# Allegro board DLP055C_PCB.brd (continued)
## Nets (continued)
GND: C1.2 C2.1 C5.1 C6.1 C7.1 C8.2 C10.1 C14.2 C15.1 C18.1 C27.1 C34.2 C58.2 C59.2 C60.1 C69.1 C70.1 C71.2 C74.2 C91.2 C95.2 C96.2 C97.2 C108.2 C109.2 C110.2 C124.2 C126.2 C127.2 C130.2 C133.2 C136.2 C137.2 C138.1 C141.2 C147.2 C148.2 C149.2 C150.2 C151.1 C152.1 C153.2 C154.2 C155.2 C156.2 C157.2 C158.2 C159.2 C160.2 C161.1 C162.2 C163.2 C164.2 C165.2 C166.2 C167.2 C168.2 C169.2 C170.1 C171.2 C172.1 C173.2 C174.2 C175.1 C176.2 C177.2 C178.2 C179.2 C180.2 C181.2 C182.2 C183.2 C184.2 C185.2 C186.2 C187.2 C188.2 C189.2 C190.2 C191.2 C192.2 C193.2 C194.2 C195.2 C196.2 C197.2 C198.2 C199.2 C200.2 C201.2 C202.1 C203.2 C204.2 C205.2 C206.2 C207.2 C208.2 C209.2 C210.1 C211.1 C212.2 C213.2 C214.2 C215.2 C216.1 C217.2 C218.2 C219.2 C220.2 C221.2 C222.2 C223.2 C224.2 C225.2 C226.2 C227.2 C228.2 C229.2 C230.2 C231.1 C232.1 C233.2 C234.2 C235.2 C236.2 C237.2 C238.2 C239.2 C240.1 C241.2 C242.2 C243.2 C244.2 C245.2 C246.2 C247.2 C248.2 C249.2 C250.2 C251.2 C252.2 C253.2 C254.2 C255.2 C256.2 C257.2 C258.2 C259.1 C260.2 C261.2 C262.2 C263.2 C264.2 C265.2 C266.2 C267.2 C268.2 C269.2 C275.2 C276.2 C277.2 C278.2 C279.2 C280.2 C281.2 C282.2 C283.2 C284.2 C285.2 C286.2 C287.2 C288.2 C289.2 C290.2 C291.2 C298.1 C299.1 C300.2 C301.2 C302.2 C303.2 C304.2 C317.2 C320.2 C321.1 C502.1 C503.1 C504.1 C507.1 C508.1 C511.2 C514.2 C515.2 C517.2 C519.2 C520.1 C521.2 C528.1 C529.2 C530.1 C531.1 C547.2 C548.1 C549.2 C557.1 C576.1 C583.2 C585.2 C622.2 C623.2 C624.2 C625.2 C654.1 C664.1 C665.2 C666.1 C667.1 C668.2 C669.2 C670.2 C675.1 C676.1 C677.2 C678.2 C679.2 C682.1 C683.1 C684.1 C687.1 C688.1 C689.1 C690.1 C692.2 C694.2 C695.1 C696.1 C697.1 C698.1 C699.2 C700.1 C753.1 C754.1 C755.1 C757.2 C758.2 C759.2 C760.2 C761.2 C762.2 C763.2 C764.1 C765.1 C766.1 C770.1 C771.1 C772.1 C774.1 C775.1 C776.1 C778.2 C779.1 C783.1 C784.1 C785.1 C786.1 C788.1 C789.1 C790.1 C792.2 C793.1 C797.1 C798.1 C799.1 C800.1 C801.2 C802.2 C803.2 C804.2 C805.2 C806.1 C807.1 C808.1 C809.1 C810.1 C811.1 C814.1 C815.1 C816.1 C817.1 C818.1 C819.1 C820.2 C821.2 C822.2 C823.2 C824.2 C825.2 C826.2 C827.1 C828.1 C829.1 C830.1 C831.1 C832.1 C833.1 C834.1 C835.1 C836.1 C837.1 D30.1(ANODE) D32.1(ANODE) D35.1(ANODE) D36.1(ANODE) D37.1(ANODE) D38.1(ANODE) D39.1(ANODE) D40.1(ANODE) D41.1(ANODE) D42.1(ANODE) D43.1(ANODE) D44.1(ANODE) D45.1(ANODE) D46.1(ANODE) D47.1(ANODE) D48.1(ANODE) D50.3(ANODE) D51.1(ANODE) DN1.1 DN2.1 DN3.1 DN4.1 DN5.1 DN6.1 DN7.1 DN8.1 DN9.1 DN10.1 DN11.1 DN12.1 FB3.1 FB4.1 J2.5(GND) J2.6(C1) J2.7(C2) J2.8(C3) J2.9(C4) J3.5 J3.6 J3.8 J3.10 J3.15 J3.19 J3.24 J3.27 J3.30 J3.33 J3.36 J3.39 J3.42 J3.45 J3.48 J3.51 J3.52(GND#52) J3.53(GND#53) J3.54(GND#54) J3.55(GND#55) J3.56(GND#56) J3.57(GND#57) J3.58(GND#58) J3.59(GND#59) J3.60(GND#60) J3.61(GND#61) J3.62(GND#62) J3.63(GND#63) J4.2 J5.2 J6.1 J6.10 J7.1 J7.4 J7.5 J7.8 J7.9 J7.12 J7.13 J7.16 J7.17 J7.20 J7.21 J7.24 J7.25 J7.28 J7.29 J7.32 J7.33 J7.36 J7.39 J7.42 J7.52(GND#52) J7.53(GND#53) J7.54(GND#54) J7.55(GND#55) J7.56(GND#56) J7.57(GND#57) J7.58(GND#58) J7.59(GND#59) J7.60(GND#60) J7.61(GND#61) J7.62(GND#62) J7.63(GND#63) J8.2 J9.2 J10.1 J10.4 J10.5 J10.8 J10.9 J10.12 J10.13 J10.16 J10.17 J10.20 J10.21 J10.24 J10.25 J10.28 J10.29 J10.32 J10.33 J10.36 J10.39 J10.42 J10.50 J10.51 J10.52(GND#52) J10.53(GND#53) J10.54(GND#54) J10.55(GND#55) J10.56(GND#56) J10.57(GND#57) J10.58(GND#58) J10.59(GND#59) J10.60(GND#60) J10.61(GND#61) J10.62(GND#62) J10.63(GND#63) J11.2 J12.4 J16.4 J17.8(P8) J17.13(P13) J17.14(P14) J20.6 J21.1 J22.2 J23.1 J27.2 J28.3 J28.5 J28.7 J28.9 J28.11 J42.5 J42.6 J42.7 J42.9 J42.12 J42.15 J42.18 J42.21 J42.24 J42.27 J42.30 J42.33 J42.36 J42.39 J42.42 J42.45 J42.48 J42.52(GND#52) J42.53(GND#53) J42.54(GND#54) J42.55(GND#55) J42.56(GND#56) J42.57(GND#57) J42.58(GND#58) J42.59(GND#59) J42.60(GND#60) J42.61(GND#61) J42.62(GND#62) J42.63(GND#63) J43.14 J44.5 J44.6 J44.7 J44.8 J44.10 J44.13 J44.16 J44.19 J44.22 J44.25 J44.27 J44.33 J44.39 J44.43 J44.45 J44.48 J44.52(GND#52) J44.53(GND#53) J44.54(GND#54) J44.55(GND#55) J44.56(GND#56) J44.57(GND#57) J44.58(GND#58) J44.59(GND#59) J44.60(GND#60) J44.61(GND#61) J44.62(GND#62) J44.63(GND#63) J45.2 J51.3 J62.2 J69.9 J69.10 J69.14 J70.9(P9) J73.1 J74.4 J83.4(GND) J83.5(C1) J83.6(C2) J85.3 J96.12 J97.7 J97.10 J97.15 J97.16 J102.5 J103.1 J104.1 J105.1 J110.1 J110.14 J111.6(P6) J112.6(P6) J113.6(P6) J114.3 J115.1 J120.6 J120.10 J120.11 J120.12 J121.6 J121.10 J121.11 J121.12 J122.7 J500.1 J500.3 J500.5 J500.7 J500.9 J500.11 J500.13 J500.15 J500.17 J500.19 J500.21 J500.23 J500.25 J500.27 J500.29 J500.31 J500.33 J500.35 J500.37 J500.39 J500.41 J500.43 J500.45 J500.47 J500.49 J500.51 J500.52(GND#52) J500.53(GND#53) J500.54(GND#54) J500.55(GND#55) J500.56(GND#56) J500.57(GND#57) J500.58(GND#58) J500.59(GND#59) J500.60(GND#60) J500.61(GND#61) J500.62(GND#62) J500.63(GND#63) J501.4 J501.6 J501.8 J501.10 J501.12 J501.14 J501.16 J501.18 J501.20 J503.1 J506.2 J516.2 J517.2 J518.2 J520.2 J521.2 J522.2 J524.2 J525.2 J526.2 J532.3 J533.3 J535.3 J536.4 Q1.2(E) Q6.2(SOURCE) Q13.2(SOURCE) R2.2(N2) R11.2(N2) R36.2(N2) R62.2(N2) R63.2(N2) R88.2(N2) R90.1(N1) R95.1(N1) R96.1(N1) R97.1(N1) R99.1(N1) R100.1(N1) R101.1(N1) R103.1(N1) R105.2(N2) R106.2(N2) R108.1 R113.1(N1) R114.1(N1) R120.2(N2) R123.2(N2) R133.2(N2) R138.2(N2) R144.2(N2) R145.2(N2) R148.2(N2) R149.2(N2) R155.1(N1) R157.2(N2) R198.1 R210.2(N2) R523.2(N2) R524.1(N1) R525.1(N1) R544.2(N2) R545.2(N2) R581.1(N1) R586.1(N1) R590.1(N1) R593.1(N1) R594.1(N1) R595.1(N1) R629.2(N2) R632.2(N2) R640.2(N2) R642.2(N2) R643.2(N2) R644.2(N2) R645.2(N2) R646.2(N2) R648.2(N2) R649.2(N2) R660.2(N2) R661.2(N2) R662.2(N2) R663.2(N2) R664.2(N2) R665.2(N2) R666.2(N2) R667.2(N2) R712.2(N2) R713.2(N2) R714.2(N2) R715.2(N2) R747.1 R751.1 R776.1 R797.1 R818.1 R821.1 R827.1 R828.2 R829.1 R830.2 R838.2 R839.1 R859.2(N2) R865.2(N2) SW5.3 TP1.1(P1) TP2.1(P1) TP11.1(P1) TP14.1(P1) TP38.1(P1) TP39.1(P1) U1.4(GND) U2.3(GND) U3.3(GND) U4.33(GND#33) U4.52(GND#52) U7.2(PGND) U7.5(GND) U7.11(PAD) U8.33(GND#33) U8.52(GND#52) U9.1(O\E\) U9.3(GND) U11.3(GND) U12.3(GND) U13.3(GND) U14.3(GND) U15.A1(VSS#A1) U15.A2(VSS#A2) U15.A3(VSS#A3) U15.A5(VSS#A5) U15.A7(VSS#A7) U15.A9(VSS#A9) U15.A11(VSS#A11) U15.A13(VSS#A13) U15.A15(VSS#A15) U15.A18(VSS#A18) U15.A20(VSS#A20) U15.A22(VSS#A22) U15.A24(VSS#A24) U15.A26(VSS#A26) U15.A28(VSS#A28) U15.A29(USB_XI) U15.A30(VSS#A30) U15.AA25(VSS#AA25) U15.AA28(VSS#AA28) U15.AB1(VSS#AB1) U15.AB6(VSS#AB6) U15.AB30(VSS#AB30) U15.AC3(VSS#AC3) U15.AC25(VSS#AC25) U15.AC27(VSS#AC27) U15.AD6(VSS#AD6) U15.AE1(VSS#AE1) U15.AE5(VSS#AE5) U15.AE7(VSS#AE7) U15.AE9(VSS#AE9) U15.AE11(VSS#AE11) U15.AE15(VSS#AE15) U15.AE17(VSS#AE17) U15.AE21(VSS#AE21) U15.AE23(VSS#AE23) U15.AE25(VSS#AE25) U15.AE26(VSS#AE26) U15.AE28(VSS#AE28) U15.AF3(VSS#AF3) U15.AF5(VSS#AF5) U15.AF6(VSS#AF6) U15.AF8(VSS#AF8) U15.AF10(VSS#AF10) U15.AF12(VSS#AF12) U15.AF14(VSS#AF14) U15.AF15(VSS#AF15) U15.AF17(VSS#AF17) U15.AF18(VSS#AF18) U15.AF19(VSS#AF19) U15.AF20(VSS#AF20) U15.AF22(VSS#AF22) U15.AF24(VSS#AF24) U15.AF26(VSS#AF26) U15.AF28(VSS#AF28) U15.AF30(VSS#AF30) U15.AG4(VSS#AG4) U15.AG6(VSS#AG6) U15.AG8(VSS#AG8) U15.AG10(VSS#AG10) U15.AG12(VSS#AG12) U15.AG14(VSS#AG14) U15.AG16(VSS#AG16) U15.AG18(VSS#AG18) U15.AG23(VSS#AG23) U15.AG25(VSS#AG25) U15.AG27(VSS#AG27) U15.AG29(VSS#AG29) U15.AH1(VSS#AH1) U15.AH2(VSS#AH2) U15.AH3(VSS#AH3) U15.AH4(VSS#AH4) U15.AH6(VSS#AH6) U15.AH8(VSS#AH8) U15.AH10(VSS#AH10) U15.AH12(VSS#AH12) U15.AH14(VSS#AH14) U15.AH16(VSS#AH16) U15.AH18(VSS#AH18) U15.AH21(VSS#AH21) U15.AH23(VSS#AH23) U15.AH25(VSS#AH25) U15.AH27(VSS#AH27) U15.AH29(VSS#AH29) U15.AH30(VSS#AH30) U15.AJ1(VSS#AJ1) U15.AJ3(VSS#AJ3) U15.AJ5(VSS#AJ5) U15.AJ7(VSS#AJ7) U15.AJ9(VSS#AJ9) U15.AJ11(VSS#AJ11) U15.AJ13(VSS#AJ13) U15.AJ15(VSS#AJ15) U15.AJ17(VSS#AJ17) U15.AJ22(VSS#AJ22) U15.AJ24(VSS#AJ24) U15.AJ26(VSS#AJ26) U15.AJ28(VSS#AJ28) U15.AJ30(VSS#AJ30) U15.AK1(VSS#AK1) U15.AK3(VSS#AK3) U15.AK5(VSS#AK5) U15.AK7(VSS#AK7) U15.AK9(VSS#AK9) U15.AK11(VSS#AK11) U15.AK13(VSS#AK13) U15.AK15(VSS#AK15) U15.AK17(VSS#AK17) U15.AK22(VSS#AK22) U15.AK24(VSS#AK24) U15.AK26(VSS#AK26) U15.AK28(VSS#AK28) U15.AK30(VSS#AK30) U15.B1(VSS#B1) U15.B2(VSS#B2) U15.B3(VSS#B3) U15.B5(VSS#B5) U15.B7(VSS#B7) U15.B9(VSS#B9) U15.B11(VSS#B11) U15.B13(VSS#B13) U15.B18(VSS#B18) U15.B20(VSS#B20) U15.B22(VSS#B22) U15.B24(VSS#B24) U15.B26(VSS#B26) U15.B28(VSS#B28) U15.B30(VSS#B30) U15.C3(VSS#C3) U15.C4(VSS#C4) U15.C6(VSS#C6) U15.C8(VSS#C8) U15.C10(VSS#C10) U15.C12(VSS#C12) U15.C14(VSS#C14) U15.C17(VSS#C17) U15.C19(VSS#C19) U15.C21(VSS#C21) U15.C23(VSS#C23) U15.C25(VSS#C25) U15.C29(VSS#C29) U15.D1(VSS#D1) U15.D2(VSS#D2) U15.D6(VSS#D6) U15.D8(VSS#D8) U15.D10(VSS#D10) U15.D12(VSS#D12) U15.D14(VSS#D14) U15.D17(VSS#D17) U15.D19(VSS#D19) U15.D21(VSS#D21) U15.D23(VSS#D23) U15.D25(VSS#D25) U15.D28(VSS#D28) U15.E3(VSS#E3) U15.E4(VSS#E4) U15.E5(VSS#E5) U15.E7(VSS#E7) U15.E9(VSS#E9) U15.E11(VSS#E11) U15.E13(VSS#E13) U15.E15(VSS#E15) U15.E20(VX1_CM_CKREF0) U15.E21(VX1_CM_CKREF1) U15.E22(VSS#E22) U15.E23(VX1_CM_CKREF2) U15.E24(VX1_CM_CKREF3) U15.E25(VSS#E25) U15.E28(VSS#E28) U15.F1(VSS#F1) U15.F2(VSS#F2) U15.F5(VSS#F5) U15.F6(VSS#F6) U15.F8(VSS#F8) U15.F10(VSS#F10) U15.F12(VSS#F12) U15.F13(VSS#F13) U15.F17(VSS#F17) U15.F18(VSS#F18) U15.F20(VSS#F20) U15.F30(VSS#F30) U15.G3(VSS#G3) U15.G4(VSS#G4) U15.G5(VSS#G5) U15.G25(VPGM) U15.G27(VSS#G27) U15.H1(VSS#H1) U15.H2(VSS#H2) U15.H5(VSS#H5) U15.H6(VSS#H6) U15.J3(VSS#J3) U15.J4(VSS#J4) U15.J5(VSS#J5) U15.J25(VSS#J25) U15.J28(VSS#J28) U15.K6(VSS#K6) U15.K30(VSS#K30) U15.L1(VSS#L1) U15.L25(VSS#L25) U15.L26(HWTEST_EN) U15.L27(VSS#L27) U15.M3(VSS#M3) U15.M6(VSS#M6) U15.M12(VSS#M12) U15.M13(VSS#M13) U15.M14(VSS#M14) U15.M15(VSS#M15) U15.M16(VSS#M16) U15.M17(VSS#M17) U15.M18(VSS#M18) U15.M19(VSS#M19) U15.M26(ICTSE) U15.N1(VSS#N1) U15.N12(VSS#N12) U15.N13(VSS#N13) U15.N14(VSS#N14) U15.N15(VSS#N15) U15.N16(VSS#N16) U15.N17(VSS#N17) U15.N18(VSS#N18) U15.N19(VSS#N19) U15.N25(VSS#N25) U15.N28(VSS#N28) U15.P6(VSS#P6) U15.P12(VSS#P12) U15.P13(VSS#P13) U15.P14(VSS#P14) U15.P15(VSS#P15) U15.P16(VSS#P16) U15.P17(VSS#P17) U15.P18(VSS#P18) U15.P19(VSS#P19) U15.P30(VSS#P30) U15.R3(VSS#R3) U15.R12(VSS#R12) U15.R13(VSS#R13) U15.R14(VSS#R14) U15.R15(VSS#R15) U15.R16(VSS#R16) U15.R17(VSS#R17) U15.R18(VSS#R18) U15.R19(VSS#R19) U15.R25(VSS#R25) U15.R27(VSS#R27) U15.T1(VSS#T1) U15.T6(VSS#T6) U15.T12(VSS#T12) U15.T13(VSS#T13) U15.T14(VSS#T14) U15.T15(VSS#T15) U15.T16(VSS#T16) U15.T17(VSS#T17) U15.T18(VSS#T18) U15.T19(VSS#T19) U15.U3(VSS#U3) U15.U5(VSS#U5) U15.U12(VSS#U12) U15.U13(VSS#U13) U15.U14(VSS#U14) U15.U15(VSS#U15) U15.U16(VSS#U16) U15.U17(VSS#U17) U15.U18(VSS#U18) U15.U19(VSS#U19) U15.U25(VSS#U25) U15.U28(VSS#U28) U15.V6(VSS#V6) U15.V12(VSS#V12) U15.V13(VSS#V13) U15.V14(VSS#V14) U15.V15(VSS#V15) U15.V16(VSS#V16) U15.V17(VSS#V17) U15.V18(VSS#V18) U15.V19(VSS#V19) U15.V30(VSS#V30) U15.W1(VSS#W1) U15.W5(VSS#W5) U15.W12(VSS#W12) U15.W13(VSS#W13) U15.W14(VSS#W14) U15.W15(VSS#W15) U15.W16(VSS#W16) U15.W17(VSS#W17) U15.W18(VSS#W18) U15.W19(VSS#W19) U15.W25(VSS#W25) U15.W27(VSS#W27) U15.Y3(VSS#Y3) U15.Y6(VSS#Y6) U16.3(GND) U17.4(GND) U18.3(GND) U19.3(GND) U20.3(GND) U26.14(AVSS1) U26.19(DVSS1) U26.49(DVSS2) U26.61(VSSU) U26.68(AVSS2) U27.2(GND) U30.4(GND) U30.7(WP) U32.7(PGND#7) U32.8(PGND#8) U32.10(NC1) U32.13(AGND) U32.16(NC2) U32.18(PGND#18) U32.21(PAD) U33.3(GND) U34.2(GND) U35.13(GND) U35.17(PAD) U36.2(GND) U37.2(GND) U38.2(I) U38.3(GND) U39.3(GND) U40.3(GND) U42.3(GND) U43.1(O\E\1\) U43.12(GND) U43.13(O\E\2\) U46.15(GND) U47.1(O\E\) U47.3(GND) U48.3(GND) U49.1(O\E\1\) U49.12(GND) U49.13(O\E\2\) U51.1(1O\E\) U51.4(GND#4) U51.10(GND#10) U51.15(GND#15) U51.21(GND#21) U51.24(4O\E\) U51.25(3O\E\) U51.26(4A4) U51.27(4A3) U51.28(GND#28) U51.34(GND#34) U51.39(GND#39) U51.45(GND#45) U51.48(2O\E\) U53.2 U54.2 U55.3(GND) U58.3(GND) U59.11(THERM_PAD) U500.2(GND) U501.4(GND) U502.2(GND) U503.4(GND) U520.3(GND) U521.11(THERM_PAD) U523.2(S) U524.5(GND) U524.9(GND_PAD) U525.3(GND) U525.4(INV) U526.3(GND) U527.2(S) U528.2(S) U529.3(GND) U538.4(V-) U539.4(V-) U555.7(GND#7) U555.19(GND#19) U555.44(GND#44) U555.49(PAD) U556.7(GND#7) U556.19(GND#19) U556.44(GND#44) U556.49(PAD) U557.7(GND#7) U557.19(GND#19) U557.44(GND#44) U557.49(PAD) U558.3(GND) U559.2(GND) U560.1(A0) U560.2(A1) U560.3(A2) U560.4(GND) U561.2(GND) U562.4(VSSD#4) U562.17(VSSD#17) U562.20(VSSD#20) U562.24(VSSA) U562.33(PAD) U563.3(GND) U564.3(GND) U565.3(GND) U566.4(V-) U567.1(O\E\) U567.3(GND) U568.3(GND) U569.3(GND) VR1.1(A) VR2.1(A) VR3.1(A) X1.2(NC1) X1.4(NC2) X2.2(NC1) X2.4(NC2)
P5V: C507.2 C764.2 J28.1 J60.1 J67.1 R755.1 TP232.1
P5V_FP_FE: J42.1 J42.2 J42.3 J42.4 J60.2
P5V_VX1_FE: J3.1 J3.2 J3.3 J3.4 J67.2
P12V: C1.1 C8.1 C58.1 C59.1 C71.1 C124.1 C130.1 C802.1 C803.1 C804.1 C805.1 C806.2 C807.2 C808.2 C830.2 J4.1 J5.1 J8.1 J97.2 J114.1 J120.1 J120.2 J121.1 J121.2 R80.2(N2) R246.1(N1) TP247.1 U32.2(VIN#2) U32.3(VIN#3) U32.4(VIN#4) U32.5(VIN#5) U59.3(VIN#3) U59.4(VIN#4) U59.5(VIN#5) U522.5(D#5) U522.6(D#6) U522.7(D#7) U522.8(D#8)
P12V_CNTL_D: Q13.3(DRAIN) R825.1 R826.2
P12V_CNTL_G: C809.2 D50.2(CATHODE) D51.3(CATHODE) Q13.1(GATE) R824.1 R830.1 SW5.1
P12V_DLPA100: C752.2 C753.2 C754.2 C755.2 C773.2 C774.2 C775.2 C776.2 C787.2 C788.2 C789.2 C790.2 C821.1 C822.1 C823.1 C824.1 C825.1 C826.1 C827.2 C828.2 C829.2 DN1.2 DN2.2 DN3.2 DN4.2 DN5.2 DN6.2 DN7.2 DN8.2 DN9.2 DN10.2 DN11.2 DN12.2 R739.2 R778.2 R779.1 R780.1 R781.2 R782.1 R799.2 R800.1 R801.1 R802.2 R803.1 TP249.1 U59.6(OUT#6) U59.7(OUT#7) U59.8(OUT#8) U555.9(VBB3) U555.22(VBB1) U555.27(ISENK) U555.37(VBB2) U555.42(VBB4) U556.9(VBB3) U556.22(VBB1) U556.27(ISENK) U556.37(VBB2) U556.42(VBB4) U557.9(VBB3) U557.22(VBB1) U557.27(ISENK) U557.37(VBB2) U557.42(VBB4)
P12V_DRV: C133.1 C320.1 R80.1(N1) U35.12(VM)
P12V_REF: D50.1(REFERENCE) R823.1 R829.2
P12V_SEQ_EN: R198.2 U58.4(Y) U59.2(EN/UVLO)
P12V_SW_G: D49.1(ANODE) Q12.G(GATE) R822.1 R825.2
P12V_VIN: C60.2 C810.2 C811.2 J527.1 J528.1 Q12.D1(DRAIN1) Q12.D2(DRAIN2) R820.2 R833.2 TP245.1 U521.3(VIN#3) U521.4(VIN#4) U521.5(VIN#5) U524.8(VIN)
VBUS: TP76.1(P1) U26.65(VBUS)
VDD33_FPD: C170.2 C230.1 C255.1 C258.1 C265.1 C266.1 C267.1 C287.1 C288.1 C289.1 L506.2 U15.E6(VDD33_FPD#E6) U15.E8(VDD33_FPD#E8) U15.E10(VDD33_FPD#E10) U15.E12(VDD33_FPD#E12) U15.E14(VDD33_FPD#E14) U15.G6(VDD33_FPD#G6) U15.L11(VDD33_FPD#L11) U15.L13(VDD33_FPD#L13)
VDD115_FPD: C257.1 C259.2 C262.1 C263.1 C264.1 C284.1 C286.1 L505.1 U15.F7(VDD115_FPD#F7) U15.F9(VDD115_FPD#F9) U15.F11(VDD115_FPD#F11) U15.J6(VDD115_FPD#J6) U15.L12(VDD115_FPD#L12)
VDD115_HSSI0_PLL: C155.1 C159.1 L13.1 U15.AE22(VDD115_HSSI0_PLL)
VDD115_HSSI1_PLL: C236.1 C239.1 L24.1 U15.AE10(VDD115_HSSI1_PLL)
VDD115_PLLMA: C180.1 C182.1 L16.1 U15.AE18(VDD115_PLLMA)
VDD115_PLLMB: C224.1 C228.1 L22.1 U15.F15(VDD115_PLLMB)
VDD115_PLLS: C226.1 C229.1 L21.1 U15.F16(VDD115_PLLS)
3D_LR: J61.2 J62.1 TP212.1(P1)
3D_REF: J44.3 U15.D15(FPDC_DATAE_N)
38MHZ_I: C232.2 R118.1(N1) X2.1
38MHZ_O: C231.2 R117.1(N1) X2.3
40MHZ_CLK0: J500.26 R669.2(N2) R706.1(N1)
40MHZ_I: C69.2 R30.1(N1) X1.1
40MHZ_O: C70.2 R31.1(N1) X1.3
40MHZ_Y0: R669.1(N1) U503.3(Y0)
40MHZ_Y1: R655.1(N1) R656.1(N1) U503.8(Y1)
ACT_A_CIPO: J120.4 U51.3(1Y2)
ACT_A_CLK: J120.5 U51.5(1Y3)
ACT_A_COPI: J120.3 U51.2(1Y1)
ACT_B_CIPO: J120.8 U51.8(2Y1)
ACT_B_CLK: J120.9 U51.9(2Y2)
ACT_B_COPI: J120.7 U51.6(1Y4)
ACT_C_CIPO: J121.4 U51.12(2Y4)
ACT_C_CLK: J121.5 U51.13(3Y1)
ACT_C_COPI: J121.3 U51.11(2Y3)
ACT_D_CIPO: J121.8 U51.16(3Y3)
ACT_D_CLK: J121.9 U51.17(3Y4)
ACT_D_COPI: J121.7 U51.14(3Y2)
AFE_ARSTZ: J44.47 U15.K2(AFE_ARSTZ)
AFE_CLK: J44.44 R626.2(N2)
AFE_CLK_T: R626.1(N1) U15.K3(AFE_CLK)
AFE_IRQ: R627.1(N1) U15.K4(AFE_IRQ)
AISEN: R144.1(N1) U35.3(AISEN)
ALF_CSYNC: J44.42 TP51.1(P1) U15.J2(ALF_CSYNC)
ALF_HSYNC: J44.41 TP52.1(P1) U15.J1(ALF_HSYNC)
ALF_VSYNC: J44.40 TP53.1(P1) U15.K5(ALF_VSYNC)
AW0_DAC_ENZ: R653.1(N1) R654.1(N1) TP208.1(P1) U51.30(4A1)
AW1_DAC_ENZ: R651.1(N1) R652.1(N1) TP210.1(P1) U51.29(4A2)
AW_DAC_ENZ: R652.2(N2) R653.2(N2) U55.4(Y)
AWC0_DACCLK_0_1: J110.3 U15.AE2(GPIO_66) U51.40(2A2) U51.44(1A3)
AWC0_DACD_PWMB_0: J110.5 R135.2(N2) U15.AD4(GPIO_68) U51.47(1A1)
AWC0_DACD_PWMB_1: J110.7 U15.AD2(GPIO_70) U51.43(1A4)
AWC0_DACS_PWMA_0: J110.4 R134.2(N2) U15.AF4(GPIO_67) U51.46(1A2)
AWC0_DACS_PWMA_1: J110.6 U15.AD3(GPIO_69) U51.41(2A1)
AWC0_OUT_ENZ: J110.2 R654.2(N2) U15.AE3(GPIO_65) U55.1(A)
AWC0_PWMA_0: R134.1(N1) U35.16(AIN1)
AWC0_PWMB_0: R135.1(N1) U35.15(AIN2)
AWC1_DACCLK_0_1: J110.9 U15.AC5(GPIO_72) U51.32(3A4) U51.36(3A1)
AWC1_DACD_PWMB_0: J110.11 R137.2(N2) U15.AC2(GPIO_74) U51.38(2A3)
AWC1_DACD_PWMB_1: J110.13 U15.AD5(GPIO_76) U51.35(3A2)
AWC1_DACS_PWMA_0: J110.10 R136.2(N2) U15.AC4(GPIO_73) U51.37(2A4)
AWC1_DACS_PWMA_1: J110.12 U15.AC1(GPIO_75) U51.33(3A3)
AWC1_OUT_ENZ: J110.8 R651.2(N2) U15.AD1(GPIO_71) U55.2(B)
AWC1_PWMA_0: R136.1(N1) U35.9(BIN1)
AWC1_PWMB_0: R137.1(N1) U35.10(BIN2)
BALLAST_CNTL_PWR: J27.3 R528.2(N2)
BISEN: R133.1(N1) U35.6(BISEN)
BT656_CLK: J43.12 J44.26 J500.10 U15.K1(GPIO_87)
BT656_DATA_0: J43.2 J44.38 R536.2(N2) R537.2(N2) U15.N4(GPIO_77)
BT656_DATA_0_M: J500.24 R537.1(N1)
BT656_DATA_0_S: J500.28 R536.1(N1)
BT656_DATA_1: J43.3 J44.37 R535.2(N2) R538.2(N2) R549.1(N1) U15.N5(GPIO_78)
BT656_DATA_1_M: J500.22 R538.1(N1)
BT656_DATA_1_S: J500.30 R535.1(N1)
BT656_DATA_2: J43.4 J44.36 J500.46 U15.M1(GPIO_79)
BT656_DATA_3: J43.5 J44.35 J500.44 U15.M2(GPIO_80)
BT656_DATA_4: J43.6 J44.34 U15.M4(GPIO_81)
BT656_DATA_5: J43.7 J44.32 U15.M5(GPIO_82)
BT656_DATA_6: J43.8 J44.31 U15.L2(GPIO_83)
BT656_DATA_7: J43.9 J44.30 U15.L3(GPIO_84)
BT656_DATA_8: J43.10 J44.29 J500.14 U15.L4(GPIO_85)
BT656_DATA_9: J43.11 J44.28 J500.12 U15.L5(GPIO_86)
CAMERA_SP4: J503.4 TP217.1(P1)
COIL_AOUT1: C134.1 J14.1 J17.1(P1) U35.2(AOUT1)
COIL_AOUT2: C134.2 J14.2 J17.2(P2) U35.4(AOUT2)
COIL_BOUT1: C135.1 J15.1 J17.3(P3) U35.7(BOUT1)
COIL_BOUT2: C135.2 J15.2 J17.4(P4) U35.5(BOUT2)
CW0_INDEX: R872.1 R875.1 TP278.1 U15.AE29(CW_INDEX) U538.1(OUT)
CW0_PWM_OUT: R777.2 TP241.1 U15.AE30(CW_PWM)
CW1_INDEX: R613.1(N1) R866.1(N1) R876.1 R879.1 TP280.1 U566.7(OUT)
CW1_PWM_OUT: R798.2 TP242.1 U15.K28(GPIO_54)
CW2_INDEX: R601.1(N1) R868.1(N1) R880.1 R883.1 TP282.1 U539.1(OUT)
CW2_PWM_OUT: R819.2 TP243.1 U15.K29(GPIO_55)
CY_GPIO_0: U42.2(A) U562.25(GPIO_0)
CY_GPIO_0_DRV: R226.2(N2) U42.4(Y)
CY_GPIO_0_LED: D10.1(CATHODE) R226.1(N1)
CY_GPIO_1: U40.2(A) U562.26(GPIO_1)
CY_GPIO_1_DRV: R218.2(N2) U40.4(Y)
CY_GPIO_1_LED: D53.1(CATHODE) R218.1(N1)
CY_GPIO_2: J96.3 U562.27(SCB0_1/GPIO_2)
CY_GPIO_5: J96.4 U562.30(SCB0_4/GPIO_5)
CY_GPIO_6: J96.5 U562.31(GPIO_6) U564.2(A)
CY_GPIO_6_BUF: R217.1(N1) U564.4(Y)
CY_GPIO_7: J96.6 U562.32(GPIO_7) U563.2(A)
CY_GPIO_7_BUF: R212.1(N1) U563.4(Y)
CY_GPIO_8: R154.2(N2) TP129.1(P1) U562.2(SCB0_0/GPIO_8)
CY_GPIO_9: J84.1 R219.2(N2) U562.3(SCB0_5/GPIO_9)
CY_GPIO_10: J75.2(P2) U562.5(SCB1_0/GPIO_10)
CY_GPIO_11: J75.4(P4) U562.6(SCB1_1/GPIO_11)
CY_GPIO_12: J75.6(P6) J96.7 U562.7(SCB1_2/GPIO_12)
CY_GPIO_13: J96.8 R211.1(N1) U562.8(SCB1_3/GPIO_13)
CY_GPIO_13_T: J75.8(P8) R211.2(N2)
CY_GPIO_14: J75.10(P10) J96.9 U562.9(SCB1_4/GPIO_14)
CY_GPIO_16: TP145.1(P1) U562.13(GPIO_16)
CY_GPIO_17: J96.10 U562.21(GPIO_17)
CY_GPIO_18: J96.11 R222.2(N2)
CY_GPIO_18_T: R222.1(N1) U562.22(GPIO_18)
CY_IIC0_OE: J84.2 R155.2(N2) R219.1(N1) U561.6(OE)
CY_IIC0_SCL: R605.1(N1) U27.8(B1) U560.6(SCL) U561.8(B1) U562.28(SCB0_2/GPIO_3)
CY_IIC0_SDA: R623.1(N1) U27.1(B2) U560.5(SDA) U561.1(B2) U562.29(SCB0_3/GPIO_4)
CY_IIC_MSP_OE: R154.1(N1) U27.6(OE)
CY_MSP_SCL: U26.38(P3.1/UCB0SOMI/UCB0SCL) U27.5(A1)
CY_MSP_SDA: U26.37(P3.0/UCB0SIMO/UCB0SDA) U27.4(A2)
CY_SUSPEND: TP144.1(P1) U562.11(SUSPEND)
CY_VBUS: C625.1 J83.1(VBUS) U562.19(VBUS)
CY_VCCD: C624.1 U562.16(VCCD)
CY_WAKEUP: TP147.1(P1) U562.12(WAKEUP)
DAC_EN0Z: J122.1 TP209.1(P1) U51.19(4Y1)
DAC_EN1Z: J122.2 TP211.1(P1) U51.20(4Y2)
DAO_CLKOUT: J500.42 R678.1(N1)
DAO_DO_0: J500.38 R676.1(N1)
DAO_DO_1: J500.40 R677.1(N1)
DMD1_SPARE_43: J10.43 R670.1(N1) R671.1(N1)
DMD_DEN_ARSTZ: J7.43 R120.1(N1) R670.2(N2) U15.AK12(DMD_DEN_ARSTZ)
DMD_DMUX: J502.2 R674.1(N1)
DMD_DMUX0: J502.1 R671.2(N2)
DMD_DMUX1: J502.3
DMD_HSSI0_CLK_N: J7.18 U15.AJ25(DMD_HSSI0_CLK_N)
DMD_HSSI0_CLK_P: J7.19 U15.AK25(DMD_HSSI0_CLK_P)
DMD_HSSI0_N_0: J7.34 U15.AJ29(DMD_HSSI0_N_0)
DMD_HSSI0_N_1: J7.30 U15.AG28(DMD_HSSI0_N_1)
DMD_HSSI0_N_2: J7.26 U15.AJ27(DMD_HSSI0_N_2)
DMD_HSSI0_N_3: J7.22 U15.AG26(DMD_HSSI0_N_3)
DMD_HSSI0_N_4: J7.14 U15.AG24(DMD_HSSI0_N_4)
DMD_HSSI0_N_5: J7.10 U15.AJ23(DMD_HSSI0_N_5)
DMD_HSSI0_N_6: J7.6 U15.AG22(DMD_HSSI0_N_6)
DMD_HSSI0_N_7: J7.2 U15.AJ21(DMD_HSSI0_N_7)
DMD_HSSI0_P_0: J7.35 U15.AK29(DMD_HSSI0_P_0)
DMD_HSSI0_P_1: J7.31 U15.AH28(DMD_HSSI0_P_1)
DMD_HSSI0_P_2: J7.27 U15.AK27(DMD_HSSI0_P_2)
DMD_HSSI0_P_3: J7.23 U15.AH26(DMD_HSSI0_P_3)
DMD_HSSI0_P_4: J7.15 U15.AH24(DMD_HSSI0_P_4)
DMD_HSSI0_P_5: J7.11 U15.AK23(DMD_HSSI0_P_5)
DMD_HSSI0_P_6: J7.7 U15.AH22(DMD_HSSI0_P_6)
DMD_HSSI0_P_7: J7.3 U15.AK21(DMD_HSSI0_P_7)
DMD_HSSI1_CLK_N: J10.18 U15.AG7(DMD_HSSI1_CLK_N)
DMD_HSSI1_CLK_P: J10.19 U15.AH7(DMD_HSSI1_CLK_P)
DMD_HSSI1_N_0: J10.34 U15.AG11(DMD_HSSI1_N_0)
DMD_HSSI1_N_1: J10.30 U15.AJ10(DMD_HSSI1_N_1)
DMD_HSSI1_N_2: J10.26 U15.AG9(DMD_HSSI1_N_2)
DMD_HSSI1_N_3: J10.22 U15.AJ8(DMD_HSSI1_N_3)
DMD_HSSI1_N_4: J10.14 U15.AJ6(DMD_HSSI1_N_4)
DMD_HSSI1_N_5: J10.10 U15.AG5(DMD_HSSI1_N_5)
DMD_HSSI1_N_6: J10.6 U15.AJ4(DMD_HSSI1_N_6)
DMD_HSSI1_N_7: J10.2 U15.AJ2(DMD_HSSI1_N_7)
DMD_HSSI1_P_0: J10.35 U15.AH11(DMD_HSSI1_P_0)
DMD_HSSI1_P_1: J10.31 U15.AK10(DMD_HSSI1_P_1)
DMD_HSSI1_P_2: J10.27 U15.AH9(DMD_HSSI1_P_2)
DMD_HSSI1_P_3: J10.23 U15.AK8(DMD_HSSI1_P_3)
DMD_HSSI1_P_4: J10.15 U15.AK6(DMD_HSSI1_P_4)
DMD_HSSI1_P_5: J10.11 U15.AH5(DMD_HSSI1_P_5)
DMD_HSSI1_P_6: J10.7 U15.AK4(DMD_HSSI1_P_6)
DMD_HSSI1_P_7: J10.3 U15.AK2(DMD_HSSI1_P_7)
DMD_LS0_CLK_N: J7.41 U15.AG17(DMD_LS0_CLK_N)
DMD_LS0_CLK_P: J7.40 U15.AH17(DMD_LS0_CLK_P)
DMD_LS0_RDATA: J7.44 U15.AH13(DMD_LS0_RDATA)
DMD_LS0_WDATA_N: J7.38 U15.AJ16(DMD_LS0_WDATA_N)
DMD_LS0_WDATA_P: J7.37 U15.AK16(DMD_LS0_WDATA_P)
DMD_LS1_CLK_N: J10.41 U15.AG15(DMD_LS1_CLK_N)
DMD_LS1_CLK_P: J10.40 U15.AH15(DMD_LS1_CLK_P)
DMD_LS1_RDATA: J10.44 U15.AG13(DMD_LS1_RDATA)
DMD_LS1_WDATA_N: J10.38 U15.AJ14(DMD_LS1_WDATA_N)
DMD_LS1_WDATA_P: J10.37 U15.AK14(DMD_LS1_WDATA_P)
DMD_OK: R87.2(N2) U3.1(A)
DMD_P1P8V_EN: J10.49 R867.1(N1) TP284.1(P1)
DMD_P12V: C668.1 C669.1 C677.1 C678.1 C679.1 J7.46 J7.47 J7.48 J7.49 J7.50 J7.51 R246.2(N2)
DMD_PWR_EN: J7.45 J10.45 U15.R4(GPIO_17)
DRAIN_SEQ: R193.1 R887.2(N2) U58.2(A) U525.6(FLAG3) U526.2(EN) U529.4(Y)
DRV_MODE: R145.1(N1) U35.14(MODE)
DRV_TRQ: R138.1(N1) U35.11(TRQ)
DYN_BLK: J86.2 R859.1(N1) U47.2(I)
DYN_BLK_1: R259.2(N2) U47.4(O)
DYN_BLK_2: J114.2 R259.1(N1)
EEPROM_WP: J72.2 U560.7(WP)
EXT_ARSTZ: TP21.1(P1) U15.AF29(EXT_ARSTZ)
EXT_I2C_EN: J52.2 R586.2(N2) U559.6(OE)
EXT_I2CPWR: C511.1 F1.1(N1) J51.4
EXT_SCL: J51.2 R863.2(N2) U17.6(IO2)
EXT_SCL_T: R861.1(N1) R863.1(N1) U559.8(B1)
EXT_SDA: J51.1 R864.2(N2) U17.3(IO1)
EXT_SDA_T: R862.1(N1) R864.1(N1) U559.1(B2)
FE_3D_LR: J3.21 J42.11 J44.51 J61.1 R260.1(N1)
FE_PROJ_ON: J68.1 R88.1(N1) U565.1(A)
FE_SPR1: J3.13 TP7.1(P1)
FIELD: J44.4 U15.C15(FPDC_DATAE_P)
FP_A_A_N: J42.47 TP132.1(P1) U15.G2(FPDA_DATAA_N)
FP_A_A_P: J42.46 TP135.1(P1) U15.G1(FPDA_DATAA_P)
FP_A_B_N: J42.44 TP138.1(P1) U15.F4(FPDA_DATAB_N)
FP_A_B_P: J42.43 TP141.1(P1) U15.F3(FPDA_DATAB_P)
FP_A_C_N: J42.41 TP131.1(P1) U15.E2(FPDA_DATAC_N)
FP_A_C_P: J42.40 TP134.1(P1) U15.E1(FPDA_DATAC_P)
FP_A_CLK_N: J42.32 TP136.1(P1) U15.H4(FPDA_CLK_N)
FP_A_CLK_P: J42.31 TP139.1(P1) U15.H3(FPDA_CLK_P)
FP_A_D_N: J42.38 TP137.1(P1) U15.D4(FPDA_DATAD_N)
FP_A_D_P: J42.37 TP140.1(P1) U15.D3(FPDA_DATAD_P)
FP_A_E_N: J42.35 TP130.1(P1) U15.C2(FPDA_DATAE_N)
FP_A_E_P: J42.34 TP133.1(P1) U15.C1(FPDA_DATAE_P)
FP_B_A_N: J42.26 TP86.1(P1) U15.D5(FPDB_DATAA_N)
FP_B_A_P: J42.25 TP89.1(P1) U15.C5(FPDB_DATAA_P)
FP_B_B_N: J42.23 TP79.1(P1) U15.B6(FPDB_DATAB_N)
FP_B_B_P: J42.22 TP82.1(P1) U15.A6(FPDB_DATAB_P)
FP_B_C_N: J42.20 TP85.1(P1) U15.D7(FPDB_DATAC_N)
FP_B_C_P: J42.19 TP88.1(P1) U15.C7(FPDB_DATAC_P)
FP_B_CLK_N: J42.29 TP80.1(P1) U15.B4(FPDB_CLK_N)
FP_B_CLK_P: J42.28 TP83.1(P1) U15.A4(FPDB_CLK_P)
FP_B_D_N: J42.17 TP78.1(P1) U15.B8(FPDB_DATAD_N)
FP_B_D_P: J42.16 TP81.1(P1) U15.A8(FPDB_DATAD_P)
FP_B_E_N: J42.14 TP84.1(P1) U15.D9(FPDB_DATAE_N)
FP_B_E_P: J42.13 TP87.1(P1) U15.C9(FPDB_DATAE_P)
FPDLINK_IIC0_EN: J64.1 R590.2(N2) U36.6(OE)
FPDLINK_IIC1_EN: J64.3 R581.2(N2) U37.6(OE)
GPIO_18: J87.2 U15.R5(GPIO_18)
GPIO_18_TST_PD: J76.3 J78.3 J87.3 J89.3 R157.1(N1)
GPIO_18_TST_PU: J76.1 J78.1 J87.1 J89.1 R156.1(N1)
GPIO_19: J89.2 U15.P1(GPIO_19)
GPIO_20: J76.2 U15.P2(GPIO_20)
GPIO_21: J78.2 U15.P3(GPIO_21)
GPIO_32: R124.2(N2) U15.Y4(GPIO_32)
GPIO_33: R127.2(N2) U15.Y2(GPIO_33)
GPIO_34: R675.2(N2) U15.Y1(GPIO_34)
GPIO_35: R676.2(N2) U15.G29(GPIO_35)
GPIO_36: R613.2(N2) R677.2(N2) U15.G30(GPIO_36)
GPIO_37: R601.2(N2) R678.2(N2) U15.H26(GPIO_37)
GPIO_38: R168.2(N2) R614.2(N2) U15.H27(GPIO_38)
GPIO_39: R169.2(N2) R615.2(N2) U15.H28(GPIO_39)
GPIO_40: R18.2(N2) U15.H29(GPIO_40)
GPIO_41: R19.2(N2) U15.H30(GPIO_41)
GPIO_42: R104.2(N2) U15.J26(GPIO_42)
GPIO_43: R870.2(N2) U15.J27(GPIO_43)
GPIO_44: R871.2(N2) U15.J29(GPIO_44)
GPIO_45: R679.2(N2) R866.2(N2) R867.2(N2) U15.J30(GPIO_45)
GPIO_46: J82.2 R680.2(N2) R868.2(N2) U15.K27(GPIO_46)
GPIO_59: J505.2 U15.AG1(GPIO_59)
GPIO_59B: J505.3 R710.2(N2) R711.2(N2)
HBT_CLKOUT: J500.8 R169.1(N1)
HBT_DO: J500.6 R168.1(N1)
HDMI_CEC: J3.23 J42.49 R234.1(N1) TP47.1(P1)
HEARTBEAT: R237.2(N2) U12.2(A) U15.AA3(GPIO_28)
HEARTBEAT_DRVR: R32.2(N2) U12.4(Y)
HEARTBEAT_LED: D15.1(CATHODE) R32.1(N1)
HOLD_BOOTZ: J9.1 R119.1(N1) U15.AE4(GPIO_64)
HTPDN: J3.25 TP5.1(P1) U15.E17(VX1_HTPDN)
ICE_RSTZ: J501.15 R504.1(N1) U39.2(A)
ICTSEN: R113.2(N2) U15.K26(ICTSEN)
IIC0_SCL: J3.18 J16.1 J53.1 R147.1(N1) R585.2(N2) U15.E27(IIC0_SCL) U36.1(B2) U559.5(A1) U561.5(A1)
IIC0_SDA: J3.20 J16.2 J54.1 R146.1(N1) R599.2(N2) U15.D29(IIC0_SDA) U36.8(B1) U559.4(A2) U561.4(A2)
IIC1_SCL: J3.14 J12.1 J21.4 R140.1(N1) U15.T2(GPIO_11) U30.6(SCL) U37.1(B2)
IIC1_SDA: J3.16 J12.2 J21.3 R139.1(N1) U15.T5(GPIO_12) U30.5(SDA) U37.8(B1)
IIC2_SCL: J17.7(P7) J536.1 R79.1(N1) R124.1(N1) R142.1(N1) R885.1(N1) U34.8(B1)
IIC2_SDA: J17.6(P6) J536.2 R78.1(N1) R127.1(N1) R143.1(N1) R884.1(N1) U34.1(B2)
IIC_BUSY: J3.17 J42.51 R128.1(N1) TP6.1(P1) TP46.1(P1) TP146.1(P1) U15.V1(GPIO_58) U26.34(P2.5/TA2.2) U562.10(SCB1_5/GPIO_15)
IIC_SCL_FP: J42.10 U36.4(A2) U37.4(A2)
IIC_SDA_FP: J42.8 U36.5(A1) U37.5(A1)
IR0: J88.1 U53.1
IR0_PWR: C697.2 R257.1(N1) U53.3
IR1: J90.1 U54.1
IR1_PWR: C698.2 R258.1(N1) U54.3
J9_SP1: J44.1 TP56.1(P1)
J9_SP2: J44.2 TP55.1(P1)
J9_SP9: J44.9 TP54.1(P1)
J9_SP46: J44.46 TP50.1(P1)
J9_SP49: J44.49 TP49.1(P1)
J9_SP50: J44.50 TP48.1(P1)
J10_SP13: J43.13 TP40.1(P1)
KEYPD_11: J69.11 R857.2(N2)
KEYPD_12: J69.12 R858.2(N2)
KEYPD_13: J69.13 R152.2(N2)
KEYPD_DOWN: J69.4 R597.1(N1) U26.23(P1.2/TA0.1)
KEYPD_LED_HOT: R857.1(N1) U26.27(P1.6/TA1CLK/CBOUT)
KEYPD_LED_LMP: R858.1(N1) U26.28(P1.7/TA1.0)
KEYPD_LED_PWR: R152.1(N1) U26.29(P2.0/TA1.1)
KEYPD_LEFT: J69.5 R610.1(N1) U26.24(P1.3/TA0.2)
KEYPD_P3P3V: J69.1 J69.8 R612.2(N2)
KEYPD_PWR: J69.7 R611.1(N1) U26.26(P1.5/TA0.4)
KEYPD_RIGHT: J69.6 R598.1(N1) U26.25(P1.4/TA0.3)
KEYPD_SEL: J69.2 R596.1(N1) U26.21(P1.0/TA0CLK/ACLK)
KEYPD_UP: J69.3 R609.1(N1) U26.22(P1.1/TA0.0)
LAMPLITZ: J26.1 J27.1 R55.2(N2) R529.2(N2)
LAMPLITZ_FLTR: C10.2 R55.1(N1) TP263.1(P1) U11.2(A)
LD_SPOKE_OFFZ: R667.1(N1) TP167.1(P1) U49.8(A7)
LD_SPOKE_OFFZ_OUT: J97.18 J115.2 U49.17(Y7)
LED_EN: J106.2 J115.3
LED_EN_BLU: J97.8 J115.8 U49.21(Y3)
LED_EN_GRN: J97.6 J115.7 U49.22(Y2)
LED_EN_IR: J97.22 U49.20(Y4)
LED_EN_RED: J97.4 J115.6 U49.23(Y1)
LED_EN_UV: J97.20 U49.19(Y5)
LEDSEL_0: R666.1(N1) U15.AB3(GPIO_24) U49.2(A1)
LEDSEL_1: R665.1(N1) U15.AB2(GPIO_25) U49.3(A2)
LEDSEL_2: J530.2 R664.1(N1) U15.AA5(GPIO_26) U49.4(A3)
LEDSEL_3: R663.1(N1) U15.AA4(GPIO_27) U49.5(A4)
LEDSEL_4: R237.1(N1) R662.1(N1) U49.6(A5)
LL_FAULT: TP24.1(P1) U15.AB4(GPIO_23) U16.2(A)
LL_FAULT_DRVR: R40.2(N2) U16.4(Y)
LL_FAULT_LED: D6.1(CATHODE) R40.1(N1)
LMP_HOT: J11.1 J530.1 R511.1(N1)
LMP_TXD: R524.2(N2) R526.1(N1) R710.1(N1) U9.2(I)
LMP_TXD_BUF: J27.5 R56.2(N2)
LMP_TXD_BUF_OUT: R56.1(N1) U9.4(O)
LMP_TXD_BUF_PWR: C504.2 R52.2(N2) U9.5(VCC)
LMPCTRL: R54.2(N2) R525.2(N2) R660.1(N1) R712.1(N1) TP219.1(P1) TP264.1(P1) U15.W4(GPIO_52) U49.10(A9) U567.2(I)
LMPCTRL_B: J106.3 U48.2(A) U49.15(Y9)
LMPCTRL_BUF: R53.1(N1) U567.4(O)
LMPCTRL_BUF_PWR: C503.2 R51.2(N2) U567.5(VCC)
LMPCTRL_BUF_R: J27.6 R53.2(N2)
LMPCTRL_BZ: J106.1 R860.1(N1) U48.4(Y)
LMPCTRL_R: Q1.1(B) R54.1(N1)
LMPCTRL_Z: J26.2 Q1.3(C) R57.1(N1)
LMPCTRL_Z_R: J27.4 R57.2(N2)
LMPSTAT: R713.1(N1) TP220.1(P1) U11.4(Y) U15.W3(GPIO_53)
LMPSYNC: R261.1(N1) TP218.1(P1) U15.V5(GPIO_51) U49.9(A8)
LOCKN: D1.1(CATHODE) J3.26 R9.1(N1) TP3.1(P1) U15.E19(VX1_LOCKN)
LOCKN_LED: D1.2(ANODE) R10.1(N1)
LVDS_VREFTEST: TP159.1(P1) U15.AF16(LVDS_VREFTEST)
MSP_IIC0_SCL: J53.2 R585.1(N1) U26.47(P4.2/PM_UCB1SOMI/PM_UCB1SCL)
MSP_IIC0_SDA: J54.2 R599.1(N1) U26.46(P4.1/PM_UCB1SIMO/PM_UCB1SDA)
MSP_LED2: D52.1(CATHODE) R856.2(N2)
MSP_LED2_DRVR: R856.1(N1) U558.4(Y)
MSP_LED2_ONZ: U26.56(P5.7/TB0.1) U558.2(A)
MSP_PROJ_ON: R608.1(N1) R865.1(N1) U565.2(B)
MSP_RSTNMI: J70.11(P11) R592.2(N2) U26.76(RS\T\\\/NMI/SBWTDIO)
MSP_V18: C531.2 U26.67(V18)
MSP_VCORE: C521.1 U26.20(VCORE)
MSPIF_VCC1: J70.4(P4) R606.2(N2)
MSPIF_VCC2: J70.2(P2) R607.2(N2)
MSPJTAG_TCK: J70.7(P7) U26.75(PJ.3/TCK)
MSPJTAG_TDI: J70.3(P3) U26.73(PJ.1/TDI/TCLK)
MSPJTAG_TDO: J70.1(P1) U26.72(PJ.0/TDO)
MSPJTAG_TMS: J70.5(P5) U26.74(PJ.2/TMS)
MTR_ARSTZ: R766.1 R790.1 R811.1 TP240.1 U15.AF27(MTR_ARSTZ) U555.48(RESETZ)
NFAULT: R73.2(N2) U35.8(NFAULT)
NSLEEP: R81.1(N1) U35.1(NSLEEP)
OCLKA: R635.2(N2) R784.2 R805.2 TP236.1 U555.6(OSC)
OCLKA_T: R635.1(N1) U15.AD30(OCLKA)
OSC_38MHZ: R589.1(N1) R604.1(N1) U500.3(OUT)
OSC_40MHZ: U502.3(OUT) U503.1(CLKIN)
OUT0A: DN1.3 J515.4 R768.1 R775.1
OUT0B: DN3.3 J515.3 R769.1 R774.1
OUT0C: DN2.3 J515.2 R771.1 R773.1
OUT1A: DN5.3 J519.4 R785.1 R796.1
OUT1B: DN7.3 J519.3 R787.1 R795.1
OUT1C: DN6.3 J519.2 R792.1 R794.1
OUT2A: DN9.3 J523.4 R806.1 R817.1
OUT2B: DN11.3 J523.3 R808.1 R816.1
OUT2C: DN10.3 J523.2 R813.1 R815.1
P1P8_DRAIN_EN: R195.1 U523.1(G) U526.8(FLAG1)
P1P8V: C74.1 C95.1 C148.1 C165.1 C190.1 C201.1 C202.2 C207.1 C208.1 C210.2 C211.2 C212.1 C216.2 C220.1 C240.2 C241.1 C252.1 C261.1 C279.1 C281.1 C282.1 C291.1 C301.1 C303.1 C758.1 C759.1 C760.1 C761.1 L15.2 L19.2 L23.2 R82.1(N1) R83.1(N1) R141.1(N1) R740.2 R831.1 TP227.1 U15.AE13(VAD18_LSIF#AE13) U15.AE14(VAD18_LSIF#AE14) U15.AE16(VDD18_SCS#AE16) U15.L16(VDD18_SCS#L16) U15.R6(VDD18_SCS#R6) U15.T25(VDD18_SCS#T25) U15.Y15(VAD18_LSIF#Y15) U34.3(VCCA)
P1P15V: C34.1 C96.1 C108.1 C109.1 C110.1 C127.1 C149.1 C154.1 C156.1 C161.2 C167.1 C178.1 C186.1 C188.1 C191.1 C193.1 C195.1 C199.1 C203.1 C209.1 C213.1 C214.1 C217.1 C218.1 C222.1 C223.1 C233.1 C234.1 C235.1 C243.1 C246.1 C249.1 C250.1 C253.1 C256.1 C300.1 C302.1 C304.1 C576.2 C583.1 L11.2 L13.2 L16.2 L18.2 L21.2 L22.2 L24.2 L505.2 R64.1(N1) R65.2(N2) R66.2(N2) U15.AF7(VDD115_HSSI#AF7) U15.AF9(VDD115_HSSI#AF9) U15.AF11(VDD115_HSSI#AF11) U15.AF13(VDD115_HSSI#AF13) U15.AF21(VDD115_HSSI#AF21) U15.AF23(VDD115_HSSI#AF23) U15.AF25(VDD115_HSSI#AF25) U15.L14(VDD115#L14) U15.L20(VDD115#L20) U15.M11(VDD115#M11) U15.N20(VDD115#N20) U15.P11(VDD115#P11) U15.R20(VDD115#R20) U15.T11(VDD115#T11) U15.U20(VDD115#U20) U15.V11(VDD115#V11) U15.W20(VDD115#W20) U15.Y11(VDD115#Y11) U15.Y13(VDD115#Y13) U15.Y14(VDD115_HSSI#Y14) U15.Y17(VDD115#Y17) U15.Y19(VDD115_HSSI#Y19)
P1P15V_BST: C125.1 U32.1(BST)
P1P15V_DRAIN: Q6.1(GATE) R76.1(N1) R77.2(N2)
P1P15V_DRAIN_BUF: R77.1(N1) U33.4(Y)
P1P15V_EN: R832.2 U32.12(EN) U33.2(A) U525.7(FLAG2)
P1P15V_FB: R62.1(N1) R64.2(N2) U32.14(FB)
P1P15V_FET: Q6.3(DRAIN) R65.1(N1) R66.1(N1)
P1P15V_MODE: R61.2(N2) R63.1(N1) U32.15(MODE)
P1P15V_PG: R75.2(N2) R839.2 U32.9(PGD) U529.2(A)
P1P15V_SS: C317.1 U32.11(SS)
P1P15V_SW: C125.2 L11.1 U32.6(SW#6) U32.19(SW#19) U32.20(SW#20)
P1P15V_VCC: C126.1 R61.1(N1) U32.17(VCC)
P1P21_DRAIN_EN: R197.1 U526.6(FLAG3) U528.1(G)
P1P21V: C91.1 C164.1 C184.1 C189.1 C194.1 C215.1 C221.1 C247.1 C248.1 C254.1 C260.1 C269.1 C762.1 R744.1 R837.1 TP229.1 U15.L15(VDD12_SCS#L15) U15.N11(VDD12_SCS#N11) U15.P20(VDD12_SCS#P20) U15.U11(VDD12_SCS#U11) U15.V20(VDD12_SCS#V20) U15.Y16(VDD12_SCS#Y16)
P2.1: TP64.1(P1) U26.30(P2.1/TA1.2)
P2.2: TP66.1(P1) U26.31(P2.2/TA2CLK/SMCLK)
P2.3: TP65.1(P1) U26.32(P2.3/TA2.0)
P2.4: TP67.1(P1) U26.33(P2.4/TA2.1)
P2.6: R608.2(N2) U26.35(P2.6/RTCCLK/DMAE0)
P2.7: TP68.1(P1) U26.36(P2.7/UCB0STE/UCA0CLK)
P2P5V: Q11.4(D) R179.1 TP231.1
P3.2: TP112.1(P1) U26.39(P3.2/UCB0CLK/UCA0STE)
P3.3: TP111.1(P1) U26.40(P3.3/UCA0TXD/UCA0SIMO)
P3.4: TP113.1(P1) U26.41(P3.4/UCA0RXD/UCA0SOMI)
P3.6: TP114.1(P1) U26.43(P3.6/TB0.6)
P3.7: TP115.1(P1) U26.44(P3.7/TB0OUTH/SVMOUT)
P3P3_DRAIN_EN: R196.1 U526.7(FLAG2) U527.1(G)
P3P3V: C97.1 C136.1 C137.1 C141.1 C147.1 C150.1 C151.2 C153.1 C157.1 C158.1 C160.1 C162.1 C163.1 C166.1 C168.1 C169.1 C171.1 C173.1 C176.1 C177.1 C181.1 C185.1 C192.1 C196.1 C206.1 C237.1 C238.1 C242.1 C244.1 C245.1 C251.1 C268.1 C275.1 C276.1 C277.1 C278.1 C280.1 C283.1 C285.1 C290.1 C298.2 C299.2 C321.2 C502.2 C508.2 C514.1 C517.1 C557.2 C654.2 C664.2 C665.1 C666.2 C667.2 C670.1 C675.2 C676.2 C682.2 C683.2 C684.2 C687.2 C688.2 C689.2 C690.2 C695.2 C696.2 C699.1 C700.2 C765.2 C831.2 C833.2 C835.2 C837.2 D6.2(ANODE) D15.2(ANODE) J12.3 J16.3 J17.5(P5) J21.2 J22.1 J23.3 J28.12 J43.1 J45.1 J64.2 J73.2 J74.3 J96.2 J103.3 J104.3 J105.3 J111.1(P1) J112.1(P1) J113.1(P1) J501.1 J501.2 J503.2 J506.1 J536.3 L14.2 L17.2 L20.2 L506.1 R9.2(N2) R10.2(N2) R20.2(N2) R21.2(N2) R22.2(N2) R34.2(N2) R38.2(N2) R39.2(N2) R51.1(N1) R52.1(N1) R73.1(N1) R78.2(N2) R79.2(N2) R81.2(N2) R84.1(N1) R85.1(N1) R86.1(N1) R89.2(N2) R92.1(N1) R93.1(N1) R94.1(N1) R98.1(N1) R102.2(N2) R119.2(N2) R121.1(N1) R122.2(N2) R125.1(N1) R128.2(N2) R139.2(N2) R140.2(N2) R142.2(N2) R143.2(N2) R146.2(N2) R147.2(N2) R150.2(N2) R151.2(N2) R156.2(N2) R200.2(N2) R201.2(N2) R209.2(N2) R256.2(N2) R257.2(N2) R258.2(N2) R504.2(N2) R505.2(N2) R506.2(N2) R508.2(N2) R511.2(N2) R517.2(N2) R519.2(N2) R520.1(N1) R522.2(N2) R526.2(N2) R528.1(N1) R529.1(N1) R542.2(N2) R543.2(N2) R549.2(N2) R647.1(N1) R716.2(N2) R717.2(N2) R756.1 R763.2 R764.2 R765.2 R766.2 R767.2 R783.2 R804.2 R835.1 R843.2 R860.2(N2) R869.2(N2) R873.2 R874.2 R875.2 R877.2 R878.2 R879.2 R881.2 R882.2 R883.2 R884.2(N2) R885.2(N2) TP233.1 U4.29(VCCIO) U4.43(VCC) U8.29(VCCIO) U8.43(VCC) U11.5(PWR) U12.5(PWR) U15.AA6(VDD33#AA6) U15.AB25(VDD33#AB25) U15.AC6(VDD33#AC6) U15.AD25(VDD33#AD25) U15.AE6(VDD33#AE6) U15.AE8(VDD33_HSSI#AE8) U15.AE12(VDD33_HSSI#AE12) U15.AE20(VDD33_HSSI#AE20) U15.AE24(VDD33_HSSI#AE24) U15.H25(VDD33#H25) U15.K25(VDD33#K25) U15.L6(VDD33#L6) U15.M20(VDD33#M20) U15.M25(VDD33#M25) U15.N6(VDD33#N6) U15.P25(VDD33#P25) U15.R11(VDD33#R11) U15.T20(VDD33#T20) U15.U6(VDD33#U6) U15.V25(VDD33#V25) U15.W6(VDD33#W6) U15.W11(VDD33#W11) U15.Y12(VDD33_HSSI#Y12) U15.Y20(VDD33_HSSI#Y20) U15.Y25(VDD33#Y25) U16.5(PWR) U30.3(A2) U30.8(VCC) U34.7(VCCB) U36.3(VCCA) U36.7(VCCB) U37.3(VCCA) U37.7(VCCB) U38.5(VCC) U39.5(PWR) U43.24(VCC) U46.16(VCC) U47.5(VCC) U48.5(PWR) U49.24(VCC) U51.7(VCC#7) U51.18(VCC#18) U51.31(VCC#31) U51.42(VCC#42) U55.5(VCC) U500.1(EN) U500.4(VDD) U502.1(EN) U502.4(VDD) U503.2(1G) U503.6(VDD) U538.8(V+) U539.8(V+) U559.3(VCCA) U566.8(V+) VR1.3(B) VR2.3(B) VR3.3(B)
P3P3V_SB: C14.1 C15.2 C27.2 C515.1 C519.1 C520.2 C528.2 C529.1 C530.2 C547.1 C548.2 C549.1 C622.1 C623.1 D5.2(ANODE) D7.2(ANODE) D8.2(ANODE) D10.2(ANODE) D52.2(ANODE) D53.2(ANODE) F1.2(N2) J52.1 J72.1 J85.1 J96.1 L2.1 R1.2(N2) R13.2(N2) R75.1(N1) R76.2(N2) R87.1(N1) R153.1(N1) R193.2 R195.2 R196.2 R197.2 R592.1(N1) R596.2(N2) R597.2(N2) R598.2(N2) R605.2(N2) R606.1(N1) R607.1(N1) R609.2(N2) R610.2(N2) R611.2(N2) R612.1(N1) R623.2(N2) R628.2(N2) R832.1 R834.2 R853.2(N2) R854.2(N2) R855.2(N2) R861.2(N2) R862.2(N2) TP248.1 U2.5(VCC) U3.5(VCC) U7.3(IN) U13.5(PWR) U14.5(PWR) U17.1(VCC) U18.5(PWR) U19.5(PWR) U20.5(PWR) U26.11(AVCC1) U26.18(DVCC1) U26.50(DVCC2) U27.3(VCCA) U27.7(VCCB) U33.5(PWR) U40.5(PWR) U42.5(PWR) U58.5(PWR) U519.3(D) U520.5(PWR) U525.1(VCC) U526.1(VCC) U526.4(INV) U529.5(PWR) U558.5(PWR) U559.7(VCCB) U560.8(VCC) U561.3(VCCA) U561.7(VCCB) U562.1(VDDD#1) U562.23(VDDD#23) U563.5(PWR) U564.5(PWR) U565.5(VCC) U568.5(PWR) U569.5(PWR)
P4.0: TP116.1(P1) U26.45(P4.0/PM_UCB1STE/PM_UCA1CLK)
P4.3: TP117.1(P1) U26.48(P4.3/PM_UCB1CLK/PM_UCA1STE)
P4.4: TP118.1(P1) U26.51(P4.4/PM_UCA1TXD/PM_UCA1SIMO)
P4.5: TP119.1(P1) U26.52(P4.5/PM_UCA1RXD/PM_UCA1SOMI)
P4.6: TP120.1(P1) U26.53(P4.6/PM_NONE)
P4.7: TP121.1(P1) U26.54(P4.7/PM_NONE)
P5.0: TP267.1(P1) U26.9(P5.0/A8/VREF+/VEREF+)
P5.1: TP37.1(P1) U26.10(P5.1/A9/VREF-/VEREF-)
P5.2: TP75.1(P1) U26.69(P5.2/XT2IN)
P5.3: TP71.1(P1) U26.70(P5.3/XT2OUT)
P5.4: TP36.1(P1) U26.12(P5.4/XIN)
P5.5: TP35.1(P1) U26.13(P5.5/XOUT)
P5.6: TP122.1(P1) U26.55(P5.6/TB0.0)
P6.0: TP74.1(P1) U26.77(P6.0/CB0/A0)
P6.1: TP70.1(P1) U26.78(P6.1/CB1/A1)
P6.2: TP73.1(P1) U26.79(P6.2/CB2/A2)
P6.3: TP69.1(P1) U26.80(P6.3/CB3/A3)
P6.4: J57.1 R593.2(N2) U26.1(P6.4/CB4/A4)
P6.4_PU: J57.2 R853.1(N1)
P6.5: J56.1 R594.2(N2) U26.2(P6.5/CB5/A5)
P6.5_PU: J56.2 R854.1(N1)
P6.6: J55.1 R595.2(N2) U26.3(P6.6/CB6/A6)
P6.6_PU: J55.2 R855.1(N1)
P6.7: TP43.1(P1) U26.4(P6.7/CB7/A7)
P7.0: TP42.1(P1) U26.5(P7.0/CB8/A12)
P7.1: TP41.1(P1) U26.6(P7.1/CB9/A13)
P7.2: TP265.1(P1) U26.7(P7.2/CB10/A14)
P7.3: TP266.1(P1) U26.8(P7.3/CB11/A15)
P7.4: TP123.1(P1) U26.57(P7.4/TB0.2)
P7.5: TP124.1(P1) U26.58(P7.5/TB0.3)
P7.6: TP125.1(P1) U26.59(P7.6/TB0.4)
P7.7: TP126.1(P1) U26.60(P7.7/TB0CLK/MCLK)
P8.0: TP34.1(P1) U26.15(P8.0)
P8.1: TP33.1(P1) U26.16(P8.1)
P8.2: TP32.1(P1) U26.17(P8.2)
PAUX0: R260.2(N2) R261.2(N2) U15.AB5(GPIO_22)
PAUX7: R674.2(N2) U15.AA2(GPIO_29)
PAUX8: R235.2(N2) U15.AA1(GPIO_30)
PAUX9: R234.2(N2) U15.Y5(GPIO_31)
PDATA_C0: J44.24 U15.A10(FPDC_CLK_P)
PDATA_C1: J44.23 U15.B10(FPDC_CLK_N)
PDATA_C2: J44.21 U15.C11(FPDC_DATAA_P)
PDATA_C3: J44.20 U15.D11(FPDC_DATAA_N)
PDATA_C4: J44.18 U15.A12(FPDC_DATAB_P)
PDATA_C5: J44.17 U15.B12(FPDC_DATAB_N)
PDATA_C6: J44.15 U15.C13(FPDC_DATAC_P)
PDATA_C7: J44.14 U15.D13(FPDC_DATAC_N)
PDATA_C8: J44.12 U15.A14(FPDC_DATAD_P)
PDATA_C9: J44.11 U15.B14(FPDC_DATAD_N)
PM0_BYTEZ: R89.1(N1) U4.53(BYTE#)
PM0_RY_BYZ: TP8.1(P1) U4.17(RY/B\Y\)
PM0_WPZ: R85.2(N2) U4.16(W\P\)
PM1_BYTEZ: R102.1(N1) U8.53(BYTE#)
PM1_RY_BYZ: TP12.1(P1) U8.17(RY/B\Y\)
PM1_WPZ: R92.2(N2) U8.16(W\P\)
PM_ADDR_0: U4.31(A0) U8.31(A0) U15.T30(PM_ADDR_0)
PM_ADDR_1: U4.26(A1) U8.26(A1) U15.U26(PM_ADDR_1)
PM_ADDR_2: U4.25(A2) U8.25(A2) U15.U27(PM_ADDR_2)
PM_ADDR_3: U4.24(A3) U8.24(A3) U15.U29(PM_ADDR_3)
PM_ADDR_4: U4.23(A4) U8.23(A4) U15.U30(PM_ADDR_4)
PM_ADDR_5: U4.22(A5) U8.22(A5) U15.V29(PM_ADDR_5)
PM_ADDR_6: U4.21(A6) U8.21(A6) U15.V28(PM_ADDR_6)
PM_ADDR_7: U4.20(A7) U8.20(A7) U15.V27(PM_ADDR_7)
PM_ADDR_8: U4.10(A8) U8.10(A8) U15.V26(PM_ADDR_8)
PM_ADDR_9: U4.9(A9) U8.9(A9) U15.W30(PM_ADDR_9)
PM_ADDR_10: U4.8(A10) U8.8(A10) U15.W29(PM_ADDR_10)
PM_ADDR_11: U4.7(A11) U8.7(A11) U15.W28(PM_ADDR_11)
PM_ADDR_12: U4.6(A12) U8.6(A12) U15.W26(PM_ADDR_12)
PM_ADDR_13: U4.5(A13) U8.5(A13) U15.Y30(PM_ADDR_13)
PM_ADDR_14: U4.4(A14) U8.4(A14) U15.Y29(PM_ADDR_14)
PM_ADDR_15: U4.3(A15) U8.3(A15) U15.Y28(PM_ADDR_15)
PM_ADDR_16: U4.54(A16) U8.54(A16) U15.Y27(PM_ADDR_16)
PM_ADDR_17: U4.19(A17) U8.19(A17) U15.Y26(PM_ADDR_17)
PM_ADDR_18: U4.18(A18) U8.18(A18) U15.AA30(PM_ADDR_18)
PM_ADDR_19: U4.11(A19) U8.11(A19) U15.AA29(PM_ADDR_19)
PM_ADDR_20: U4.12(A20) U8.12(A20) U15.AA27(PM_ADDR_20)
PM_ADDR_21: U4.15(A21) U8.15(A21) U15.AA26(PM_ADDR_21)
PM_ADDR_22: U4.2(A22) U8.2(A22) U15.AB29(PM_ADDR_22)
PM_ADDR_23: U4.1(A23) U8.1(A23) U15.AB28(GPIO_47)
PM_CSZ_0: R84.2(N2) U4.32(C\E\) U15.T27(PM_CSZ_0)
PM_CSZ_1: R93.2(N2) U8.32(C\E\) U15.T28(PM_CSZ_1)
PM_DATA_0: U4.35(DQ0) U8.35(DQ0) U15.L29(PMDATA_00)
PM_DATA_1: U4.37(DQ1) U8.37(DQ1) U15.L30(PMDATA_01)
PM_DATA_2: U4.39(DQ2) U8.39(DQ2) U15.L28(PMDATA_02)
PM_DATA_3: U4.41(DQ3) U8.41(DQ3) U15.M27(PMDATA_03)
PM_DATA_4: U4.44(DQ4) U8.44(DQ4) U15.M28(PMDATA_04)
PM_DATA_5: U4.46(DQ5) U8.46(DQ5) U15.M29(PMDATA_05)
PM_DATA_6: U4.48(DQ6) U8.48(DQ6) U15.M30(PMDATA_06)
PM_DATA_7: U4.50(DQ7) U8.50(DQ7) U15.N26(PMDATA_07)
PM_DATA_8: U4.36(DQ8) U8.36(DQ8) U15.N27(PMDATA_08)
PM_DATA_9: U4.38(DQ9) U8.38(DQ9) U15.N29(PMDATA_09)
PM_DATA_10: U4.40(DQ10) U8.40(DQ10) U15.N30(PMDATA_10)
PM_DATA_11: U4.42(DQ11) U8.42(DQ11) U15.P26(PMDATA_11)
PM_DATA_12: U4.45(DQ12) U8.45(DQ12) U15.P27(PMDATA_12)
PM_DATA_13: U4.47(DQ13) U8.47(DQ13) U15.P28(PMDATA_13)
PM_DATA_14: U4.49(DQ14) U8.49(DQ14) U15.P29(PMDATA_14)
PM_DATA_15: U4.51(DQ15) U8.51(DQ15) U15.R26(PMDATA_15)
PM_OEZ: R94.2(N2) U4.34(O\E\) U8.34(O\E\) U15.R29(PM_OEZ)
PM_WEZ: R98.2(N2) R112.1(N1) U4.13(W\E\) U8.13(W\E\)
PM_WEZ_T: R112.2(N2) U15.R28(PM_WEZ)
PMD0_SPI_CIPO: R772.1 R844.2
PMD0_SPI_CLK: R847.2 U555.2(CLK)
PMD0_SPI_COPI: R840.2 U555.3(DIN)
PMD0_SPI_CSZ: R850.2 U555.4(CSZ)
PMD0_VREG: C757.1 U555.20(VREG) U555.31(FB1) U555.47(TRIM)
PMD1_SPI_CIPO: R789.1 R845.2
PMD1_SPI_CLK: R848.2 U556.2(CLK)
PMD1_SPI_COPI: R841.2 U556.3(DIN)
PMD1_SPI_CSZ: R851.2 U556.4(CSZ)
PMD1_VREG: C778.1 U556.20(VREG) U556.24(V5) U556.30(/FBC) U556.31(FB1) U556.32(FB2) U556.45(V3P3) U556.46(V2P5) U556.47(TRIM)
PMD2_SPI_CIPO: R810.1 R846.2
PMD2_SPI_CLK: R849.2 U557.2(CLK)
PMD2_SPI_COPI: R842.2 U557.3(DIN)
PMD2_SPI_CSZ: R852.2 U557.4(CSZ)
PMD2_VREG: C792.1 U557.20(VREG) U557.24(V5) U557.30(/FBC) U557.31(FB1) U557.32(FB2) U557.45(V3P3) U557.46(V2P5) U557.47(TRIM)
PMD_INTZ: R767.1 R793.1 R814.1 TP237.1 U15.AD26(PMD_INTZ) U555.36(PMDINTZ)
PMIC_PWRGOOD: R153.2(N2) R764.1 R786.1 R807.1 TP238.1 U13.2(A) U14.2(A) U555.35(PWRGOOD) U569.4(Y)
POSENSE: R86.2(N2) R765.1 R788.1 R809.1 TP239.1 U4.14(R\E\S\E\T\) U8.14(R\E\S\E\T\) U15.AE27(POSENSE) U20.2(A) U555.34(POSENSE)
POSENSE_DRVZ: R43.2(N2) U20.4(Y)
POSENSE_LED: D8.1(CATHODE) R43.1(N1)
PRIMARY_PU: J82.1 R869.1(N1)
PROJ_ON: R886.2(N2) U3.4(Y) U18.2(A) U19.2(A) U525.2(EN)
PROJ_ON_1: U2.1(A) U565.4(Y)
PROJ_ON_3: U2.4(Y) U3.2(B)
PROJ_ON_DRV: R42.2(N2) U19.4(Y)
PROJ_ON_LED: D7.1(CATHODE) R42.1(N1)
PROJ_ON_OD: R125.2(N2) U15.AG2(GPIO_63) U18.4(Y)
PU.0: TP127.1(P1) U26.62(PU.0/DP)
PU.1: TP72.1(P1) U26.64(PU.1/DM)
PUR: TP128.1(P1) U26.63(PUR)
PWM_BLU: J97.5 U43.21(Y3)
PWM_GRN: J97.3 U43.22(Y2)
PWM_IN0: J73.3 J74.2 J77.1
PWM_IN1: J73.4 J74.1 J79.1
PWM_IR: J97.9 U43.20(Y4)
PWM_OUT_BLED: R643.1(N1) U15.AF1(GPIO_61) U43.4(A3)
PWM_OUT_GLED: J98.1 R644.1(N1) U15.AF2(GPIO_60) U43.3(A2)
PWM_OUT_IRLED: R642.1(N1) U15.AG3(GPIO_62) U43.5(A4)
PWM_OUT_RLED: J505.1 R645.1(N1) U43.2(A1)
PWM_OUT_STD_0: J86.1 R640.1(N1) U15.W2(GPIO_56) U43.7(A6)
PWM_OUT_STD_1: J86.3 R632.1(N1) U15.V2(GPIO_57) U43.8(A7)
PWM_RED: J97.1 U43.23(Y1)
PWM_STD_0: J97.13 U43.18(Y6)
PWM_STD_1: J97.17 U43.17(Y7)
PWRGOOD: R121.2(N2) U13.4(Y) U15.AG30(PWRGOOD) U39.4(Y)
PWRGOOD_DRV: R37.2(N2) U14.4(Y)
PWRGOOD_LED: D5.1(CATHODE) R37.1(N1)
REFCLKA_I: R29.2(N2) R30.2(N2) R655.2(N2) R706.2(N2) U15.AJ18(REFCLKA_I)
REFCLKA_O: R29.1(N1) R31.2(N2) R656.2(N2) U15.AK18(REFCLKA_O)
REFCLKB_I: R116.2(N2) R118.2(N2) R604.2(N2) U15.B16(REFCLKB_I)
REFCLKB_O: R116.1(N1) R117.2(N2) R589.2(N2) U15.A16(REFCLKB_O)
RS232_VN: C694.1 U46.6(V-)
RTCK: J501.11 R506.1(N1) R507.2(N2)
RX0N: C72.2 J3.49
RX0P: C73.2 J3.50
RX1N: C67.2 J3.46
RX1P: C68.2 J3.47
RX2N: C65.2 J3.43
RX2P: C66.2 J3.44
RX3N: C63.2 J3.40
RX3P: C64.2 J3.41
RX4N: C61.2 J3.37
RX4P: C62.2 J3.38
RX5N: C53.2 J3.34
RX5P: C54.2 J3.35
RX6N: C49.2 J3.28
RX6P: C50.2 J3.29
RX7N: C51.2 J3.31
RX7P: C52.2 J3.32
SAS_CLK: J28.4 TP20.1(P1) U15.V4(GPIO_06)
SAS_CSZ: J28.10 TP271.1(P1) U15.U1(GPIO_09)
SAS_DI: J28.6 TP270.1(P1) U15.U4(GPIO_07)
SAS_DO: J28.8 TP268.1(P1) U15.U2(GPIO_08)
SAS_INTGTR_EN: J21.5 J28.2 TP269.1(P1) U15.V3(GPIO_10)
SECONDARY_PD: J82.3 R210.1(N1)
SENSE_PULSE_OUT: J97.12 J115.12 U49.16(Y8)
SPARE_J39_4: J115.4 TP164.1(P1)
SPARE_J39_9: J115.9 TP165.1(P1)
SPARE_J39_10: J115.10 TP166.1(P1)
SPARE_J39_11: J115.11 TP168.1(P1)
SPARE_J202_14: J97.14 TP153.1(P1)
SPARE_U32_18: J115.5 U49.18(Y6)
SPARE_U39_6: TP155.1(P1) U43.6(A5)
SPARE_U39_10: TP150.1(P1) U43.9(A8)
SPARE_U39_11: TP151.1(P1) U43.10(A9)
SPARE_U39_12: TP156.1(P1) U43.11(A10)
SPARE_U39_14: TP149.1(P1) U43.14(Y10)
SPARE_U39_15: TP154.1(P1) U43.15(Y9)
SPARE_U39_16: J97.19 U43.16(Y8)
SPARE_U39_19: J97.11 U43.19(Y5)
SPARE_U508_7: R661.1(N1) TP170.1(P1) U49.7(A6)
SPARE_U508_11: R646.1(N1) TP169.1(P1) U49.11(A10)
SPARE_U508_14: TP163.1(P1) U49.14(Y10)
SPI0_CIPO: J122.6 J506.5 R36.1(N1) R716.1(N1) R843.1 R844.1 R845.1 R846.1 TP273.1 U15.AD29(SSP0_RXD)
SPI0_CLK: J122.5 J506.3 R109.1(N1) R123.1(N1) R715.1(N1) R847.1 R848.1 R849.1 TP274.1
SPI0_CLK_T: R109.2(N2) U15.AD28(SSP0_CLK)
SPI0_COPI: J122.4 J506.4 R34.1(N1) R110.1(N1) R714.1(N1) R840.1 R841.1 R842.1 TP272.1
SPI0_COPI_T: R110.2(N2) U15.AD27(SSP0_TXD)
SPI0_CSZ_0: J506.6 R111.1(N1) R122.1(N1) R717.1(N1) R850.1 TP275.1
SPI0_CSZ_0_T: R111.2(N2) U15.AB27(SSP0_CSZ_0)
SPI0_CSZ_1: J122.3 R672.1(N1)
SPI0_CSZ_2: R673.1(N1) R851.1 TP276.1
SPI0_CSZ_3: R852.1 TP277.1 U15.AC29(GPIO_50)
SPI0_CSZ_4: U15.AC30(GPIO_49)
SPI1_CIPO: J3.9 J22.5 R150.1(N1) U15.C16(GPIO_02)
SPI1_CLK: J3.7 J22.3 R148.1(N1) U15.E16(GPIO_00)
SPI1_COPI: J3.11 J22.4 R149.1(N1) U15.D16(GPIO_01)
SPI1_CSZ_0: J3.12 J22.6 R151.1(N1) U15.B15(GPIO_03)
SPI1_CSZ_1: R38.1(N1) TP22.1(P1) U15.B17(GPIO_04)
SPI1_CSZ_2: R39.1(N1) TP23.1(P1) U15.A17(GPIO_05)
SPI2_BC_CSZ: R209.1(N1) R680.1(N1)
SPI2_CIPO: J45.4 J500.36 R19.1(N1) R105.1(N1) R544.1(N1)
SPI2_CLK: J45.3 R18.1(N1) R106.1(N1) R534.2(N2) R539.2(N2) R545.1(N1)
SPI2_CLK_M: J500.20 R539.1(N1)
SPI2_CLK_S: J500.32 R534.1(N1)
SPI2_COPI: J45.5 J500.16 R20.1(N1) R104.1(N1) R543.1(N1)
SPI2_CSZ_0: J45.6 R22.1(N1) R533.2(N2) R540.2(N2) R542.1(N1) R870.1(N1)
SPI2_CSZ_0_M: J500.18 R540.1(N1)
SPI2_CSZ_0_S: J500.34 R533.1(N1)
SPI2_CSZ_1: R21.1(N1) R200.1(N1) R546.2(N2) R550.2(N2) R871.1(N1)
SPI2_CSZ_1_M: J500.2 R550.1(N1) TP215.1(P1)
SPI2_CSZ_1_S: J500.50 R546.1(N1) TP214.1(P1)
SPI2_CSZ_2: R201.1(N1) R547.2(N2) R548.2(N2) R679.1(N1)
SPI2_CSZ_2_M: J500.4 R548.1(N1) TP216.1(P1)
SPI2_CSZ_2_S: J500.48 R547.1(N1) TP213.1(P1)
STATUS_INT: J42.50 R627.2(N2)
SUBFRAME: J97.21 TP148.1(P1)
SW_ONOFF: C585.1 J85.2 R212.2(N2) SW3.2 U26.42(P3.5/TB0.5)
SW_ONOFF_PD: R629.1(N1) SW3.1 SW3.4
SW_ONOFF_PU: R628.1(N1) SW3.3 SW3.6
SW_PROJ_ON: C138.2 R217.2(N2) SW1.2 U2.2(B)
SW_PROJ_ON_PD: R2.1(N1) SW1.1 SW1.4
SW_PROJ_ON_PU: R1.1(N1) SW1.3 SW1.6
TCK: J20.5 J75.7(P7) J501.9 R507.1(N1) R517.1(N1) U15.AK19(TCK)
TDI: J20.2 J75.3(P3) J501.5 R519.1(N1) U15.AG20(TDI)
TDO1: J20.4 J75.1(P1) U15.AG19(TDO1)
TDO2: J501.13 R505.1(N1) U15.AH19(TDO2)
TEST_SBWTCK: J70.8(P8) U26.71(TEST/SBWTCK)
TMP_IIC2_SCL: R83.2(N2) U34.5(A1)
TMP_IIC2_SDA: R82.2(N2) U34.4(A2)
TMS1: J20.3 J75.5(P5) U15.AH20(TMS1)
TMS2: J501.7 R508.1(N1) U15.AJ20(TMS2)
TMS3: R256.1(N1) U15.AK20(TMS3)
TRSTZ: R520.2(N2) U15.AG21(TRSTZ) U38.4(O)
TRSTZ_IN: J20.1 J75.9(P9) J501.3 R522.1(N1) R523.1(N1) U38.1(O\E\)
TSTPT_0: J6.2 R103.2(N2) U15.E29(TSTPT_0)
TSTPT_1: J6.3 R101.2(N2) U15.E30(TSTPT_1)
TSTPT_2: J6.4 R100.2(N2) U15.F26(TSTPT_2)
TSTPT_3: J6.5 R99.2(N2) U15.F27(TSTPT_3)
TSTPT_4: J6.6 R97.2(N2) U15.F28(TSTPT_4)
TSTPT_5: J6.7 R96.2(N2) U15.F29(TSTPT_5)
TSTPT_6: J6.8 R95.2(N2) U15.G26(TSTPT_6)
TSTPT_7: J6.9 R90.2(N2) U15.G28(TSTPT_7)
TXS_OE: R141.2(N2) U34.6(OE)
UART0_C1M: C691.1 U46.3(C1-)
UART0_C1P: C691.2 U46.1(C1+)
UART0_C2M: C693.1 U46.5(C2-)
UART0_C2P: C693.2 U46.4(C2+)
UART0_CTSZ: J23.2 J94.1 J104.2 J112.4(P4) U15.N3(UART0_CTSZ)
UART0_CTSZ_CON: J102.7 U46.13(R_IN1)
UART0_CTSZ_JUMPER: J94.2 R649.1(N1) U46.12(R_OUT1)
UART0_DCD_CON: J102.1 R668.1(N1)
UART0_DSR_CON: J102.6 R650.2(N2) R668.2(N2)
UART0_DTR_CON: J102.4 R650.1(N1)
UART0_RSTZ_CON: J102.8 U46.14(T_OUT1)
UART0_RTSZ: J23.6 J104.6 J112.5(P5) R648.1(N1) U15.N2(UART0_RTSZ) U46.11(T_IN1)
UART0_RXD: J23.5 J95.1 J104.5 J112.3(P3) U15.P5(UART0_RXD)
UART0_RXD_CON: J102.3 U46.8(R_IN2)
UART0_RXD_JUMPER: J95.2 U46.9(R_OUT2)
UART0_TXD: J23.4 J104.4 J112.2(P2) R647.2(N2) U15.P4(UART0_TXD) U46.10(T_IN2)
UART0_TXD_CON: J102.2 U46.7(T_OUT2)
UART0_VP: C692.1 U46.2(V+)
UART1_CTSZ: J105.2 J113.4(P4) U15.R1(GPIO_15)
UART1_RTSZ: J105.6 J113.5(P5) U15.R2(GPIO_16)
UART1_RXD: J105.5 J113.3(P3) U15.T3(GPIO_14)
UART1_TXD: J105.4 J113.2(P2) U15.T4(GPIO_13)
UART2_RXD: J98.2 J103.5 J111.3(P3) R615.1(N1)
UART2_TXD: J103.4 J111.2(P2) R614.1(N1) R711.1(N1)
USB_AUX: C5.2 R91.1(N1) U7.10(AUX)
USB_DAT_N: R4.1(N1) U15.A27(USB_DAT_N)
USB_DAT_N_IN: J2.2(DM) R4.2(N2) U1.5(IO2)
USB_DAT_P: R5.1(N1) U15.B27(USB_DAT_P)
USB_DAT_P_IN: J2.3(DP) R5.2(N2) U1.3(IO1)
USB_EN: R13.1(N1) R14.1(N1) U7.4(EN)
USB_ENUSB: R8.1(N1) U7.7(ENUSB)
USB_FAULTZ: R91.2(N2) TP9.1(P1) U7.8(F\A\U\L\T\)
USB_ID: J2.4(ID) TP286.1(P1) U15.C27(USB_ID)
USB_ILIM: R11.1(N1) U7.6(ILIM)
USB_OTG_CP_EN: R8.2(N2) R14.2(N2) U15.AB26(GPIO_48)
USB_SW: L2.2 U7.1(SW)
USB_TXRTUNE: R114.2(N2) U15.C26(USB_TXRTUNE)
USB_VBUS: C2.2 C6.2 C7.2 J2.1(VBUS) U7.9(USB) U15.D26(USB_VBUS)
USBDM: J83.2(DM) U501.5(IO2) U562.15(USBDM)
USBDP: J83.3(DP) U501.3(IO1) U562.14(USBDP)
UVLO_PWRDWN_1: R886.1(N1) U520.4(Y)
UVLO_PWRDWN_2: R887.1(N1) U568.4(Y)
VAD18_PLLMA: C179.1 C183.1 L15.1 U15.AE19(VAD18_PLLMA)
VAD18_PLLMB: C225.1 C227.1 L23.1 U15.F14(VAD18_PLLMB)
VAD18_VX1: C197.1 C204.1 C205.1 L19.1 U15.E18(VAD18_VX1#E18) U15.L19(VAD18_VX1#L19)
VAD33_OSCA: C187.1 L17.1 U15.Y18(VAD33_OSCA)
VAD33_OSCB: C219.1 L20.1 U15.L17(VAD33_OSCB)
VAD33_USB: C152.2 C172.2 C175.2 L14.1 U15.D27(VAD33_USB#D27) U15.E26(VAD33_USB#E26) U15.F25(VAD33_USB#F25)
VAD115_VX1: C174.1 C198.1 C200.1 L18.1 U15.F24(VAD115_VX1#F24) U15.L18(VAD115_VX1#L18)
VBIAS_MON: J10.47 R235.1(N1) TP285.1(P1)
VUSB: TP77.1(P1) U26.66(VUSB)
VX1_CM_AMOUT0: TP106.1(P1) U15.F19(VX1_CM_AMOUT0)
VX1_CM_AMOUT1: TP107.1(P1) U15.F21(VX1_CM_AMOUT1)
VX1_CM_AMOUT2: TP108.1(P1) U15.F22(VX1_CM_AMOUT2)
VX1_CM_AMOUT3: TP109.1(P1) U15.F23(VX1_CM_AMOUT3)
VX1_DATA0_N: C72.1 U15.D18(VX1_DATA0_N)
VX1_DATA0_P: C73.1 U15.C18(VX1_DATA0_P)
VX1_DATA1_N: C67.1 U15.B19(VX1_DATA1_N)
VX1_DATA1_P: C68.1 U15.A19(VX1_DATA1_P)
VX1_DATA2_N: C65.1 U15.D20(VX1_DATA2_N)
VX1_DATA2_P: C66.1 U15.C20(VX1_DATA2_P)
VX1_DATA3_N: C63.1 U15.B21(VX1_DATA3_N)
VX1_DATA3_P: C64.1 U15.A21(VX1_DATA3_P)
VX1_DATA4_N: C61.1 U15.D22(VX1_DATA4_N)
VX1_DATA4_P: C62.1 U15.C22(VX1_DATA4_P)
VX1_DATA5_N: C53.1 U15.B23(VX1_DATA5_N)
VX1_DATA5_P: C54.1 U15.A23(VX1_DATA5_P)
